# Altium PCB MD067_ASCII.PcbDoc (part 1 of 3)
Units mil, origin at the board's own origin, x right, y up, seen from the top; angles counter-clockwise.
Board outline 3650 x 4750 mil, 4 copper layers (Top Layer, GND Layer, Power Layer, Bottom Layer), stack 58.4 mil thick; 234 components, 118 nets, 586 pads, 972 vias.
Unrouted connection lines stored in the file: 42.
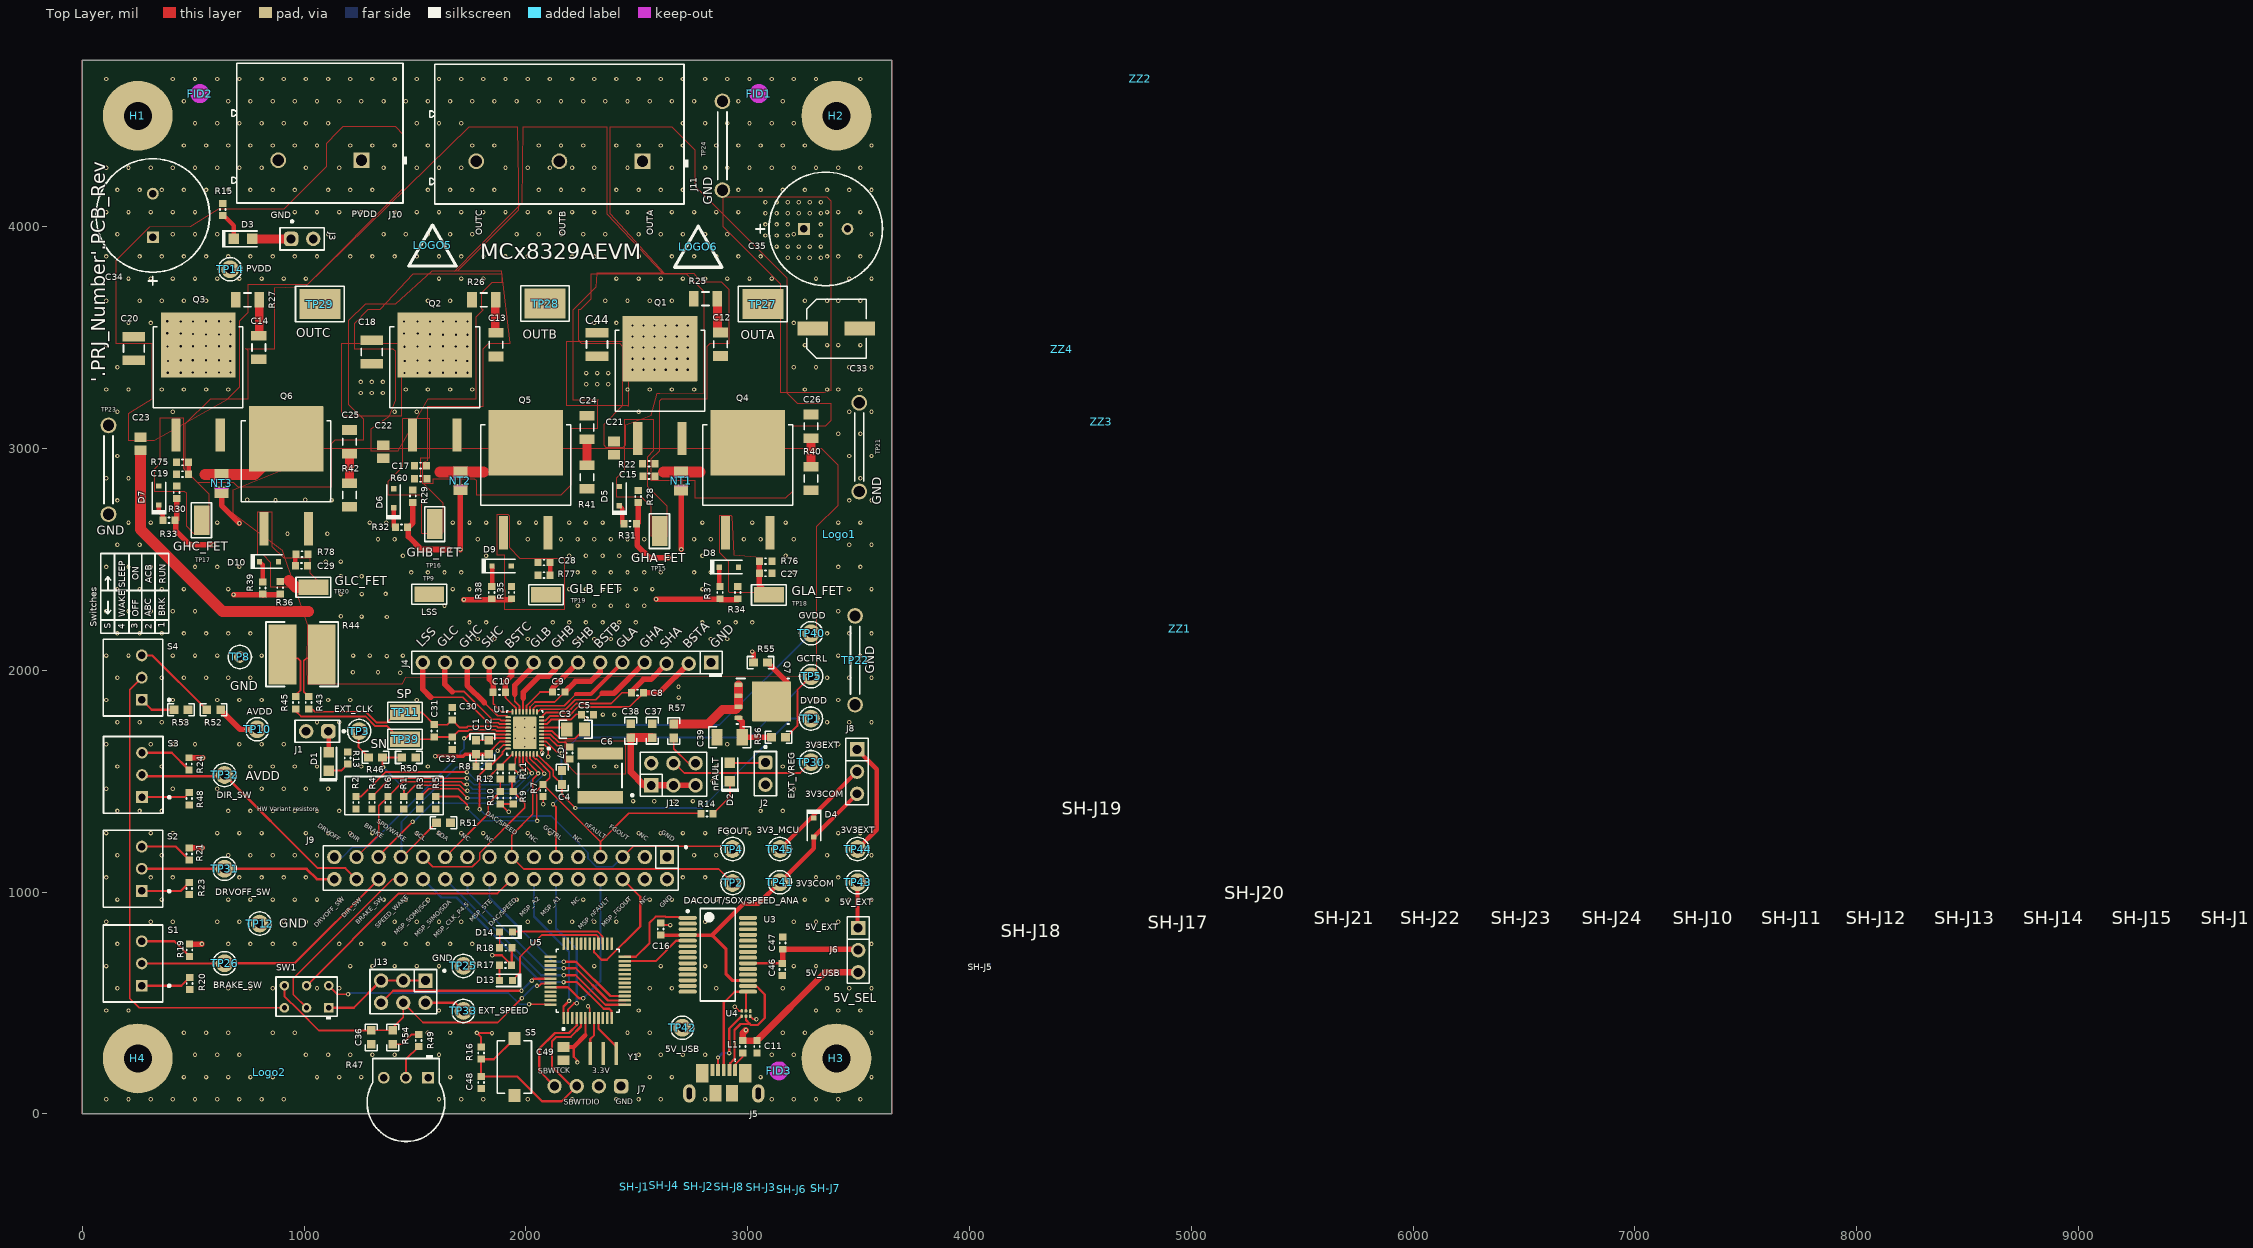
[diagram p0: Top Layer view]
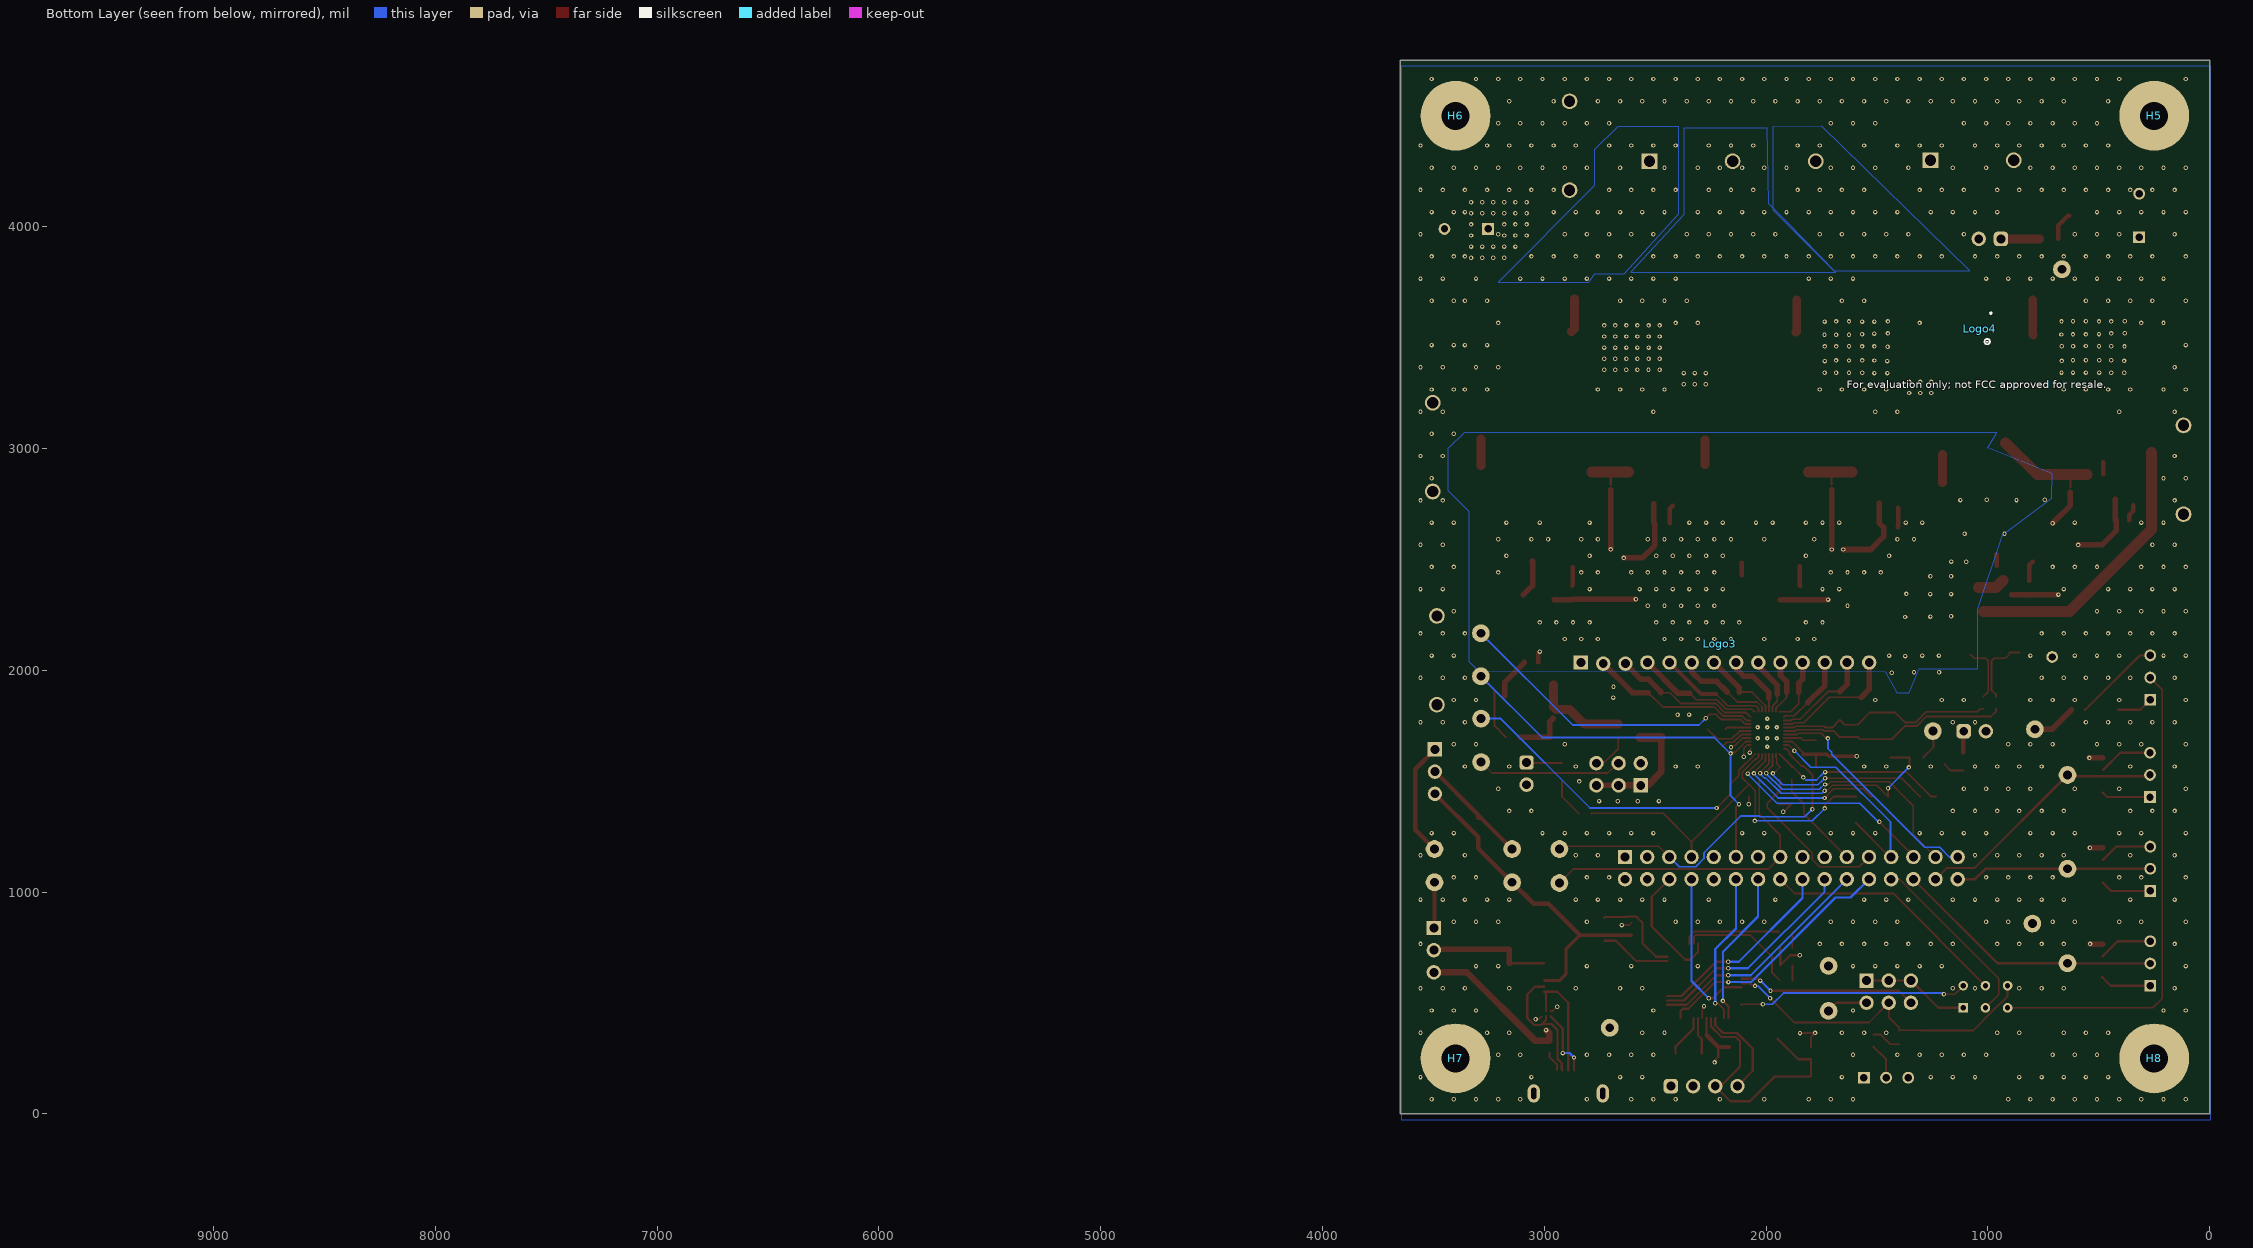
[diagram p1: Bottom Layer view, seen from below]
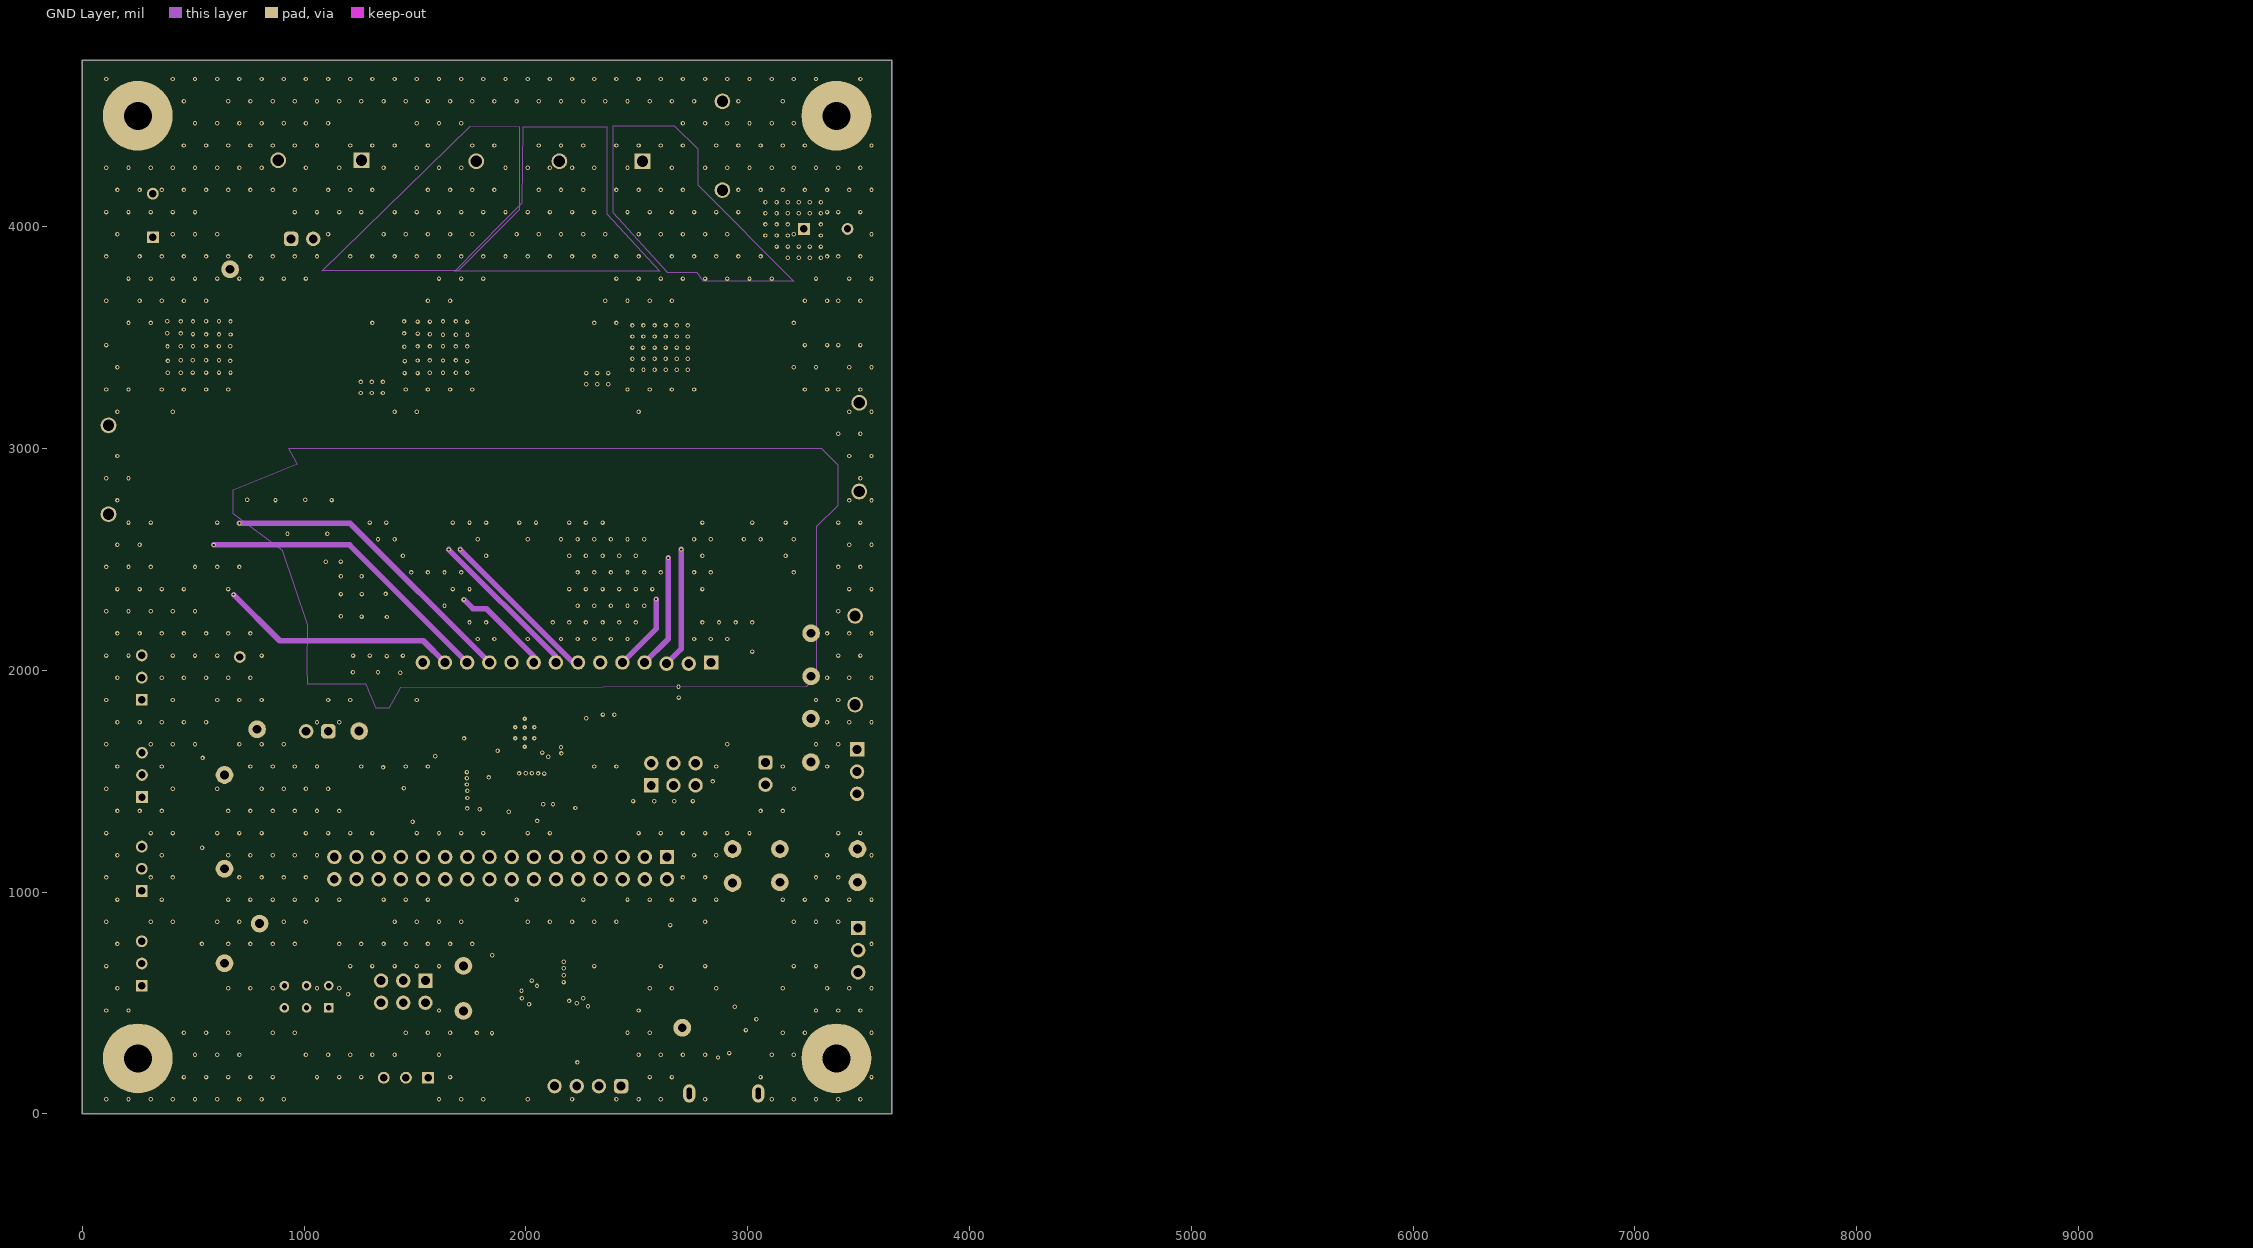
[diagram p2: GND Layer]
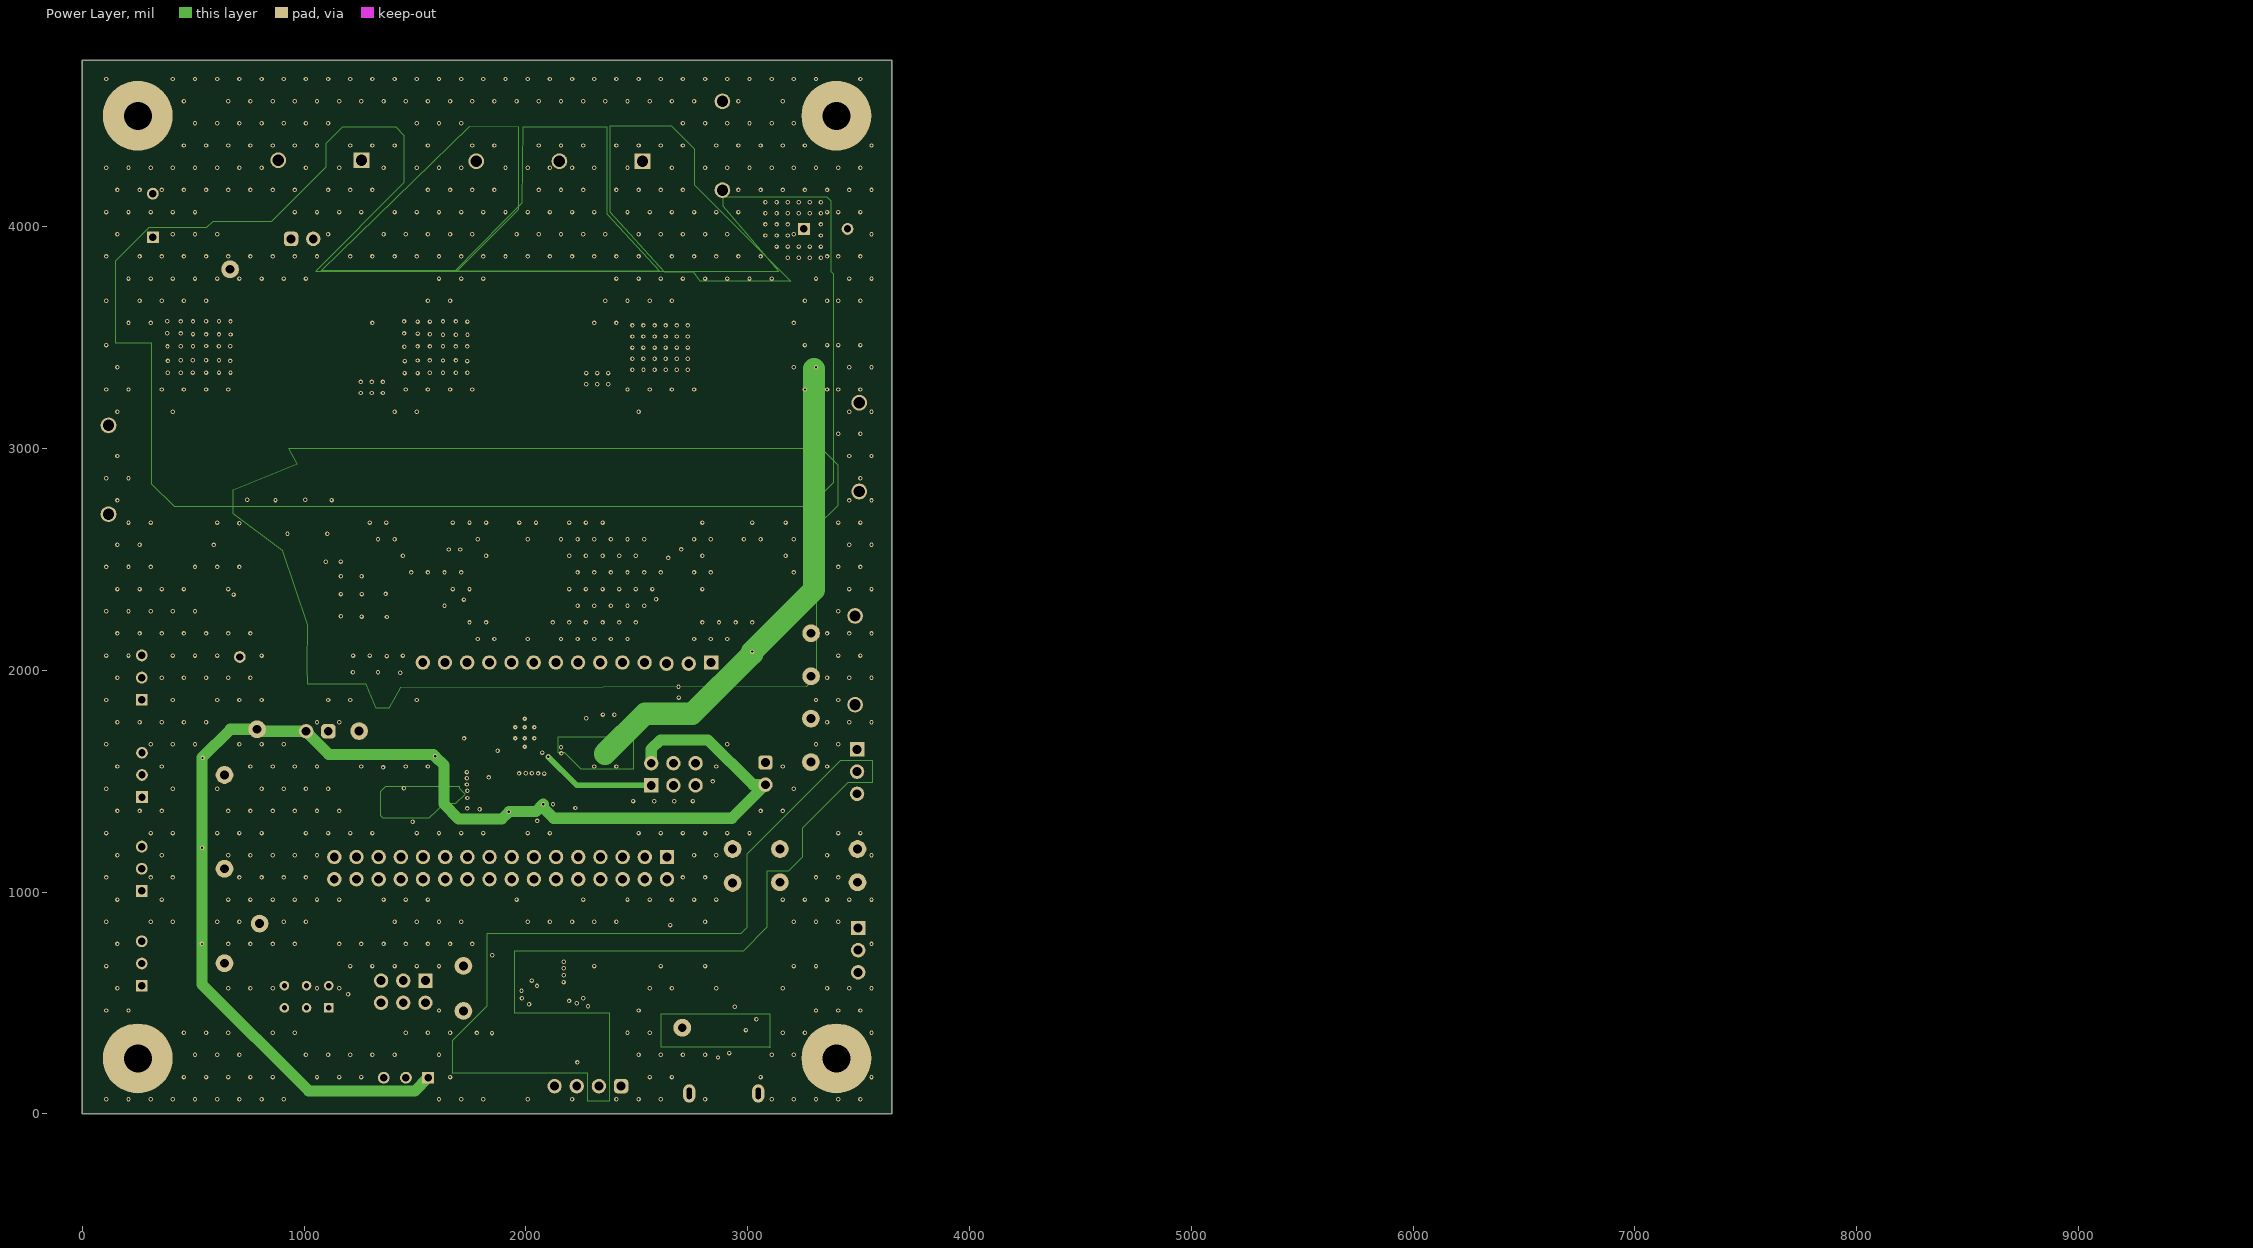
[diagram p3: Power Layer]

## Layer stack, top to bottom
Top Solder: solder mask 0.4, Solder Resist, Dk 3.5
Top Layer: signal copper 2.8
Dielectric 2: core 10, FR-4, Dk 4.8
GND Layer: signal copper 1.4
Dielectric 1: prepreg 30, FR-4, Dk 4.2
Power Layer: signal copper 1.4
Dielectric 3: core 10, FR-4, Dk 4.8
Bottom Layer: signal copper 2.8
Solder Side: solder mask 0.4, Solder Resist, Dk 3.5

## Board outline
0,0 3650,0 3650,4750 0,4750

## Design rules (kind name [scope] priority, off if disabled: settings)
AcuteAngle [All] p0: scope1count=1 scope1_0_kind=Board scope1_0_value=Board scope2count=1 scope2_0_kind=Board scope2_0_value=Board commentlength=0 minimum=4.50000000000000E+0001
AcuteAngle [All] p1: minimum=4.50000000000000E+0001 checktracksonly=FALSE
AssemblyTestPointUsage [All] p0: scope1count=1 scope1_0_kind=Board scope1_0_value=Board scope2count=1 scope2_0_kind=Board scope2_0_value=Board commentlength=0
AssemblyTestPointUsage [All] p1: valid=2
AssemblyTestpoint [All] p0: scope1count=1 scope1_0_kind=Board scope1_0_value=Board scope2count=1 scope2_0_kind=Board scope2_0_value=Board commentlength=0
BoardOutlineClearance [All] p0 off: scope1count=1 scope1_0_kind=Board scope1_0_value=Board scope2count=1 scope2_0_kind=Board scope2_0_value=Board commentlength=172 gap=50 // Protel DXP Scope 1 Expression Was: OnCopper and Not InComponentClass('Logo') and not InComponentClass('FiducialMark') and not InRegion(1000,500,4000,800) and not InPoly
BoardOutlineClearance BoardOutlineClearance_Poly [All] p0 off: scope1count=1 scope1_0_kind=Board scope1_0_value=Board scope2count=1 scope2_0_kind=Board scope2_0_value=Board commentlength=58 gap=25 // Protel DXP Scope 1 Expression Was: OnCopper and IsPoly
BoardOutlineClearance BoardOutlineClearance_MountingHoles [All] p0 off: scope1count=1 scope1_0_kind=Board scope1_0_value=Board scope2count=1 scope2_0_kind=Board scope2_0_value=Board commentlength=86 gap=39.37 // Protel DXP Scope 1 Expression Was: OnCopper and InComponentClass('Mounting Holes')
BoardOutlineClearance BoardOutlineClearance_MountingHoles [OnCopper and InComponentClass('Mounting Holes')] p1: gap=39.37 ignorepadtopadclearanceinfootprint=FALSE
BoardOutlineClearance BoardOutlineClearance_Poly [OnCopper and IsPoly] p2: gap=25 ignorepadtopadclearanceinfootprint=FALSE
BoardOutlineClearance [OnCopper and Not InComponentClass('Logo') and not InComponentClass('FiducialMark') and not InRegion(1000,500,4000,800) and not InPoly] p3: gap=50 ignorepadtopadclearanceinfootprint=FALSE
Clearance [All] p0: scope1count=1 scope1_0_kind=Board scope1_0_value=Board scope2count=1 scope2_0_kind=Board scope2_0_value=Board commentlength=0 gap=7.87
Clearance Clearance_FiducialMark [All] p0 off: scope1count=1 scope1_0_kind=Board scope1_0_value=Board scope2count=1 scope2_0_kind=Board scope2_0_value=Board commentlength=81 gap=0 // Protel DXP Scope 2 Expression Was: IsPad and InComponentClass('FiducialMark')
Clearance Clearance_Poly [All] p0 off: scope1count=1 scope1_0_kind=Board scope1_0_value=Board scope2count=1 scope2_0_kind=Board scope2_0_value=Board commentlength=48 gap=10 // Protel DXP Scope 1 Expression Was: InPolygon
Clearance Clearance_Keepouts [All] p0 off: scope1count=1 scope1_0_kind=Board scope1_0_value=Board scope2count=1 scope2_0_kind=Board scope2_0_value=Board commentlength=99 gap=0 // Protel DXP Scope 2 Expression Was: ((IsTrack Or IsArc) And Not InPoly) And IsFree and IsKeepOut
Clearance Clearance_Keepouts [((IsTrack Or IsArc) And Not InPoly) And IsFree and IsKeepOut vs ((IsTrack Or IsArc) And Not InPoly) And IsFree and IsKeepOut] p1: gap=0 ignorepadtopadclearanceinfootprint=FALSE
Clearance Clearance_Poly [InPolygon] p2: gap=10 ignorepadtopadclearanceinfootprint=TRUE
Clearance Clearance_FiducialMark [IsKeepOut and InComponentClass('FiducialMark') vs IsPad and InComponentClass('FiducialMark')] p3: gap=0 ignorepadtopadclearanceinfootprint=FALSE
Clearance [All] p4: gap=7.87 ignorepadtopadclearanceinfootprint=TRUE
ComponentClearance [All] p0: scope1count=1 scope1_0_kind=Board scope1_0_value=Board scope2count=1 scope2_0_kind=Board scope2_0_value=Board commentlength=0 gap=30 collisioncheckmode=3
ComponentClearance ComponentClearance_THtoTH [All] p0 off: scope1count=1 scope1_0_kind=Board scope1_0_value=Board scope2count=1 scope2_0_kind=Board scope2_0_value=Board commentlength=54 gap=30 collisioncheckmode=3 // Protel DXP Scope 2 Expression Was: IsThruComponent
ComponentClearance ComponentClearance_THtoSMT [All] p0 off: scope1count=1 scope1_0_kind=Board scope1_0_value=Board scope2count=1 scope2_0_kind=Board scope2_0_value=Board commentlength=53 gap=40 collisioncheckmode=3 // Protel DXP Scope 2 Expression Was: IsSMTComponent
ComponentClearance ComponentClearance_SmallPassives [All] p0 off: scope1count=1 scope1_0_kind=Board scope1_0_value=Board scope2count=1 scope2_0_kind=Board scope2_0_value=Board commentlength=508 gap=14.96 collisioncheckmode=3 // Protel DXP Scope 2 Expression Was: HasFootprint('0201*') or HasFootprint('0402*') or HasFootprint('0508') or HasFootprint('0603*') or HasFootprint('0612') or HasFootprint('0805*') or HasFootprint('0815*') or HasFootprint('0830*') or HasFootprint('1206*') or HasFootprint('1210*') or HasFootprint('1808*') or HasFootprint('1812*') or HasFootprint('1825*') or HasFootprint('2010*') or HasFootprint('2220*') or HasFootprint('2225*') or HasFootprint('2512*') or HasFootprint('2728*') or HasFootprint('3518*')
ComponentClearance ComponentClearance_MountingHoles [All] p0: scope1count=1 scope1_0_kind=ComponentClass scope1_0_value="Mounting Holes" scope2count=1 scope2_0_kind=Board scope2_0_value=Board commentlength=0 gap=10 collisioncheckmode=3
ComponentClearance ComponentClearance_ScrewToNut [All] p0 off: scope1count=1 scope1_0_kind=Board scope1_0_value=Board scope2count=1 scope2_0_kind=Board scope2_0_value=Board commentlength=71 gap=5 collisioncheckmode=3 // Protel DXP Scope 2 Expression Was: (HasFootprint('Keystone_1902C'))
ComponentClearance ComponentClearance_Logo [All] p0: scope1count=1 scope1_0_kind=ComponentClass scope1_0_value=Logo scope2count=1 scope2_0_kind=Board scope2_0_value=Board commentlength=0 gap=20 collisioncheckmode=3
ComponentClearance ComponentClearance_Shunt [All] p0: scope1count=1 scope1_0_kind=ComponentClass scope1_0_value=Header scope2count=1 scope2_0_kind=ComponentClass scope2_0_value=Shunt commentlength=0 gap=0 collisioncheckmode=3
ComponentClearance ComponentClearance_MountingHoles_FiducialMarks [All] p0: scope1count=1 scope1_0_kind=ComponentClass scope1_0_value="Mounting Holes" scope2count=1 scope2_0_kind=ComponentClass scope2_0_value=FiducialMark commentlength=0 gap=50 collisioncheckmode=3
ComponentClearance ComponentClearance_MountingHoles_FiducialMarks [InComponentClass('Mounting Holes') vs InComponentClass('FiducialMark')] p1: gap=50 collisioncheckmode=3 verticalgap=10 showdistances=FALSE
ComponentClearance ComponentClearance_Shunt [InComponentClass('Header') vs InComponentClass('Shunt')] p2: gap=0 collisioncheckmode=3 verticalgap=0 showdistances=FALSE
ComponentClearance ComponentClearance_Logo [InComponentClass('Logo')] p3: gap=20 collisioncheckmode=3 verticalgap=10 showdistances=FALSE
ComponentClearance ComponentClearance_ScrewToNut [(HasFootprint('NY PMS 440 0025 PH')) vs (HasFootprint('Keystone_1902C'))] p4: gap=5 collisioncheckmode=3 verticalgap=10 showdistances=FALSE
ComponentClearance ComponentClearance_MountingHoles [InComponentClass('Mounting Holes')] p5: gap=10 collisioncheckmode=3 verticalgap=100000 showdistances=FALSE
ComponentClearance ComponentClearance_SmallPassives [HasFootprint('0201*') or HasFootprint('0402*') or HasFootprint('0508') or HasFootprint('0603*') or HasFootprint('0612') or HasFootprint('0805*') or HasFootprint('0815*') or HasFootprint('0830*') or HasFootprint('1206*') or HasFootprint('1210*') or HasFootprint('1808*') or HasFootprint('1812*') or HasFootprint('1825*') or HasFootprint('2010*') or HasFootprint('2220*') or HasFootprint('2225*') or HasFootprint('2512*') or HasFootprint('2728*') or HasFootprint('3518*') vs HasFootprint('0201*') or HasFootprint('0402*') or HasFootprint('0508') or HasFootprint('0603*') or HasFootprint('0612') or HasFootprint('0805*') or HasFootprint('0815*') or HasFootprint('0830*') or HasFootprint('1206*') or HasFootprint('1210*') or HasFootprint('1808*') or HasFootprint('1812*') or HasFootprint('1825*') or HasFootprint('2010*') or HasFootprint('2220*') or HasFootprint('2225*') or HasFootprint('2512*') or HasFootprint('2728*') or HasFootprint('3518*')] p6: gap=14.96 collisioncheckmode=3 verticalgap=10 showdistances=FALSE
ComponentClearance ComponentClearance_THtoSMT [IsThruComponent vs IsSMTComponent] p7: gap=40 collisioncheckmode=3 verticalgap=30 showdistances=FALSE
ComponentClearance ComponentClearance_THtoTH [IsThruComponent vs IsThruComponent] p8: gap=30 collisioncheckmode=3 verticalgap=30 showdistances=FALSE
ComponentClearance [All] p9: gap=30 collisioncheckmode=3 verticalgap=10 showdistances=FALSE
DiffPairsRouting [All] p0: scope1count=1 scope1_0_kind=Board scope1_0_value=Board scope2count=1 scope2_0_kind=Board scope2_0_value=Board commentlength=0
DiffPairsRouting [All] p1: maxlimit=100 minlimit=10 mostfreqgap=10 toplayer_minwidth=15 toplayer_maxwidth=15 toplayer_prefwidth=15 midlayer1_minwidth=15 midlayer1_maxwidth=15 midlayer1_prefwidth=15 midlayer2_minwidth=15 midlayer2_maxwidth=15 midlayer2_prefwidth=15 bottomlayer_minwidth=15 bottomlayer_maxwidth=15 bottomlayer_prefwidth=15 maxuncoupledlength=1000
FabricationTestPointUsage TestPointUsage [All] p0: scope1count=1 scope1_0_kind=Board scope1_0_value=Board scope2count=1 scope2_0_kind=Board scope2_0_value=Board commentlength=0 valid=2 allowmultiple=FALSE
FabricationTestPointUsage TestPointUsage [All] p1: valid=2 allowmultiple=FALSE
FabricationTestpoint Testpoint [All] p0: scope1count=1 scope1_0_kind=Board scope1_0_value=Board scope2count=1 scope2_0_kind=Board scope2_0_value=Board commentlength=0 side=3 testpointundercomponent=TRUE minsize=40 maxsize=100 preferedsize=60 minholesize=0 maxholesize=40 preferedholesize=32 testpointgrid=1
FabricationTestpoint Testpoint [All] p1: side=3 testpointundercomponent=TRUE minsize=40 maxsize=100 preferedsize=60 minholesize=0 maxholesize=40 preferedholesize=32 testpointgrid=1 allowsidetop=TRUE allowsidebottom=TRUE usegrid=TRUE gridtolerance=0.01
FanoutControl Fanout_Small [All] p0 off: scope1count=1 scope1_0_kind=Board scope1_0_value=Board scope2count=1 scope2_0_kind=Board scope2_0_value=Board commentlength=84 // Protel DXP Scope 1 Expression Was: (CompPinCount < 5)   Fanout_Small (Default Rule)
FanoutControl Fanout_Default [All] p0: scope1count=1 scope1_0_kind=Board scope1_0_value=Board scope2count=1 scope2_0_kind=Board scope2_0_value=Board commentlength=30 // Fanout_Default (Default Rule)
FanoutControl Fanout_SOIC [All] p0 off: scope1count=1 scope1_0_kind=Board scope1_0_value=Board scope2count=1 scope2_0_kind=Board scope2_0_value=Board commentlength=71 // Protel DXP Scope 1 Expression Was: IsSOIC   Fanout_SOIC (Default Rule)
FanoutControl Fanout_BGA [All] p0 off: scope1count=1 scope1_0_kind=Board scope1_0_value=Board scope2count=1 scope2_0_kind=Board scope2_0_value=Board commentlength=69 // Protel DXP Scope 1 Expression Was: IsBGA   Fanout_BGA (Default Rule)
FanoutControl Fanout_LCC [All] p0 off: scope1count=1 scope1_0_kind=Board scope1_0_value=Board scope2count=1 scope2_0_kind=Board scope2_0_value=Board commentlength=69 // Protel DXP Scope 1 Expression Was: IsLCC   Fanout_LCC (Default Rule)
FanoutControl Fanout_LCC [IsLCC] p1: bgadir=Out bgaviamode=Centered fanoutstyle=Auto fanoutdirection=Alternating viagrid=1 // Fanout_LCC (Default Rule)
FanoutControl Fanout_BGA [IsBGA] p2: bgadir=Out bgaviamode=Centered fanoutstyle=Auto fanoutdirection=Alternating viagrid=1 // Fanout_BGA (Default Rule)
FanoutControl Fanout_Default [All] p4: bgadir=Out bgaviamode=Centered fanoutstyle=Auto fanoutdirection=Alternating viagrid=1 // Fanout_Default (Default Rule)
FanoutControl Fanout_Small [(CompPinCount < 5)] p5: bgadir=Out bgaviamode=Centered fanoutstyle=Auto fanoutdirection=OutThenIn viagrid=1 // Fanout_Small (Default Rule)
Height [All] p0 off: scope1count=1 scope1_0_kind=Board scope1_0_value=Board scope2count=1 scope2_0_kind=Board scope2_0_value=Board commentlength=0
Height [All] p1 off: minheight=0 maxheight=1000 prefheight=500
HoleSize [All] p0: scope1count=1 scope1_0_kind=Board scope1_0_value=Board scope2count=1 scope2_0_kind=Board scope2_0_value=Board commentlength=0 absolutevalues=TRUE maxlimit=250 minlimit=7.87 maxpercent=80.000 minpercent=20.000
HoleSize [All] p1: absolutevalues=TRUE maxlimit=250 minlimit=7.87 maxpercent=80.000 minpercent=20.000
HoleToHoleClearance [All] p0: scope1count=1 scope1_0_kind=Board scope1_0_value=Board scope2count=1 scope2_0_kind=Board scope2_0_value=Board commentlength=0
LayerPairs [All] p0: scope1count=1 scope1_0_kind=Board scope1_0_value=Board scope2count=1 scope2_0_kind=Board scope2_0_value=Board commentlength=0 enforce=TRUE
MinimumAnnularRing [All] p0: scope1count=1 scope1_0_kind=Board scope1_0_value=Board scope2count=1 scope2_0_kind=Board scope2_0_value=Board commentlength=0 minimumring=5
MinimumAnnularRing MinimumAnnularRing_ThermalPadVias [All] p0 off: scope1count=1 scope1_0_kind=Board scope1_0_value=Board scope2count=1 scope2_0_kind=Board scope2_0_value=Board commentlength=63 minimumring=5 // Protel DXP Scope 1 Expression Was: IsVia and InAnyComponent
MinimumAnnularRing MinimumAnnularRing_ThermalPadVias [IsVia and InAnyComponent] p1: minimumring=5
MinimumAnnularRing [All] p2: minimumring=5
MinimumSolderMaskSliver [All] p0: scope1count=1 scope1_0_kind=Board scope1_0_value=Board scope2count=1 scope2_0_kind=Board scope2_0_value=Board commentlength=0
MinimumSolderMaskSliver MinimumSolderMaskSliver_Logo [All] p0: scope1count=1 scope1_0_kind=ComponentClass scope1_0_value=Logo scope2count=1 scope2_0_kind=ComponentClass scope2_0_value=Logo commentlength=0
MinimumSolderMaskSliver MinimumSolderMaskSliver_Logo [InComponentClass('Logo') vs InComponentClass('Logo')] p1: minsoldermaskwidth=0.7
MinimumSolderMaskSliver [All] p2: minsoldermaskwidth=3.94
NetAntennae [All] p0: scope1count=1 scope1_0_kind=Board scope1_0_value=Board scope2count=1 scope2_0_kind=Board scope2_0_value=Board commentlength=0
PasteMaskExpansion [All] p0: scope1count=1 scope1_0_kind=Board scope1_0_value=Board scope2count=1 scope2_0_kind=Board scope2_0_value=Board commentlength=0 expansion=0
PlaneClearance [All] p0: scope1count=1 scope1_0_kind=Board scope1_0_value=Board scope2count=1 scope2_0_kind=Board scope2_0_value=Board commentlength=0 clearance=20
PlaneConnect [All] p0: scope1count=1 scope1_0_kind=Board scope1_0_value=Board scope2count=1 scope2_0_kind=Board scope2_0_value=Board commentlength=0 planeconnectstyle=Relief reliefexpansion=10 reliefentries=4 reliefconductorwidth=10 reliefairgap=10
PlaneConnect [All] p1: planeconnectstyle=Relief reliefexpansion=10 reliefentries=4 reliefconductorwidth=10 reliefairgap=10
PolygonConnect PolygonConnect_1 [All] p0: scope1count=1 scope1_0_kind=Board scope1_0_value=Board scope2count=1 scope2_0_kind=Board scope2_0_value=Board commentlength=0 connectstyle=Direct reliefconductorwidth=10 reliefentries=4 polygonreliefangle="90 Angle"
PolygonConnect PolygonConnect_1 [All] p1: connectstyle=Direct reliefconductorwidth=10 reliefentries=4 polygonreliefangle="90 Angle" airgapwidth=10
RoutingCorners [All] p0: scope1count=1 scope1_0_kind=Board scope1_0_value=Board scope2count=1 scope2_0_kind=Board scope2_0_value=Board commentlength=0 cornerstyle=45-Degree minsetback=100 maxsetback=100
RoutingLayers [All] p0: scope1count=1 scope1_0_kind=Board scope1_0_value=Board scope2count=1 scope2_0_kind=Board scope2_0_value=Board commentlength=0 top layer=Automatic mid layer 1=Automatic mid layer 2=Automatic bottom layer=Automatic
RoutingPriority [All] p0: scope1count=1 scope1_0_kind=Board scope1_0_value=Board scope2count=1 scope2_0_kind=Board scope2_0_value=Board commentlength=0
RoutingTopology [All] p0: scope1count=1 scope1_0_kind=Board scope1_0_value=Board scope2count=1 scope2_0_kind=Board scope2_0_value=Board commentlength=0 topology=Shortest
RoutingVias [All] p0: scope1count=1 scope1_0_kind=Board scope1_0_value=Board scope2count=1 scope2_0_kind=Board scope2_0_value=Board commentlength=0 holewidth=10 width=20 viastyle="Through Hole" minholewidth=10 minwidth=20 maxholewidth=10 maxwidth=20
RoutingVias ThermalPadVias [All] p0 off: scope1count=1 scope1_0_kind=Board scope1_0_value=Board scope2count=1 scope2_0_kind=Board scope2_0_value=Board commentlength=63 holewidth=7.87 width=19.68 viastyle="Through Hole" minholewidth=7.87 minwidth=19.68 maxholewidth=12.99 maxwidth=23.62 // Protel DXP Scope 1 Expression Was: IsVia and InAnyComponent
RoutingVias ThermalPadVias [IsVia and InAnyComponent] p1: holewidth=7.87 width=19.68 viastyle="Through Hole" minholewidth=7.87 minwidth=19.68 maxholewidth=12.99 maxwidth=23.62
RoutingVias [All] p2: holewidth=10 width=20 viastyle="Through Hole" minholewidth=10 minwidth=20 maxholewidth=10 maxwidth=20
ShortCircuit [All] p0: scope1count=1 scope1_0_kind=Board scope1_0_value=Board scope2count=1 scope2_0_kind=Board scope2_0_value=Board commentlength=0 allowed=FALSE
SilkToBoardRegionClearance [All] p0 off: scope1count=1 scope1_0_kind=Board scope1_0_value=Board scope2count=1 scope2_0_kind=Board scope2_0_value=Board commentlength=130 // Protel DXP Scope 1 Expression Was: Not ((IsComment or IsDesignator) And (Hide <> 'False')) and not InRegion(1000,500,4000,800)
SilkToBoardRegionClearance [Not ((IsComment or IsDesignator) And (Hide <> 'False')) and not InRegion(1000,500,4000,800)] p1:
SilkToSilkClearance [All] p0: scope1count=1 scope1_0_kind=Board scope1_0_value=Board scope2count=1 scope2_0_kind=Board scope2_0_value=Board commentlength=0
SilkToSilkClearance SilkToSilkClearance_Pb-FreeLogo [All] p0 off: scope1count=1 scope1_0_kind=Board scope1_0_value=Board scope2count=1 scope2_0_kind=Board scope2_0_value=Board commentlength=120 // Protel DXP Scope 2 Expression Was: (HasFootprint('Pb-Free_Overlay_Medium') OR HasFootprint('Pb-Free_Overlay_Small'))
SilkToSilkClearance SilkToSilkClearance_Pb-FreeLogo [(HasFootprint('Pb-Free_Overlay_Medium') OR HasFootprint('Pb-Free_Overlay_Small')) vs (HasFootprint('Pb-Free_Overlay_Medium') OR HasFootprint('Pb-Free_Overlay_Small'))] p1: silktosilkclearance=0
SilkToSilkClearance [All] p2: silktosilkclearance=1
SilkToSolderMaskClearance "Silk to Solder Mask Opening" [All] p0: scope1count=1 scope1_0_kind=Board scope1_0_value=Board scope2count=1 scope2_0_kind=Board scope2_0_value=Board commentlength=0
SilkToSolderMaskClearance SilkToComponentPadClearance [All] p0 off: scope1count=1 scope1_0_kind=Board scope1_0_value=Board scope2count=1 scope2_0_kind=Board scope2_0_value=Board commentlength=87 // Protel DXP Scope 1 Expression Was: (IsPad or IsFill or IsRegion) and InAnycomponent
SilkToSolderMaskClearance SilkToComponentPadClearance [(IsPad or IsFill or IsRegion) and InAnycomponent] p1: minsilkscreentomaskgap=2 clearancetoexposedcopper=TRUE
SilkToSolderMaskClearance "Silk to Solder Mask Opening" [All] p2: minsilkscreentomaskgap=3.94 clearancetoexposedcopper=FALSE
SolderMaskExpansion [All] p0: scope1count=1 scope1_0_kind=Board scope1_0_value=Board scope2count=1 scope2_0_kind=Board scope2_0_value=Board commentlength=0 expansion=1.97
SolderMaskExpansion [All] p1: expansion=1.97
UnRoutedNet [All] p0: scope1count=1 scope1_0_kind=Board scope1_0_value=Board scope2count=1 scope2_0_kind=Board scope2_0_value=Board commentlength=0
UnRoutedNet [All] p1: checkbadconnections=TRUE
UnpouredPolygon [All] p0: scope1count=1 scope1_0_kind=Board scope1_0_value=Board scope2count=1 scope2_0_kind=Board scope2_0_value=Board commentlength=0
Width [All] p0: scope1count=1 scope1_0_kind=Board scope1_0_value=Board scope2count=1 scope2_0_kind=Board scope2_0_value=Board commentlength=0 maxlimit=100 minlimit=6 preferedwidth=10
Width [All] p1: maxlimit=100 minlimit=6 preferedwidth=10 checkconnectedcopper=TRUE
13 further rules are at their usual default settings.

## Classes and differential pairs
component class MD067_INTERFACE: C11 C16 C46 C47 C48 C49 D4 D13 D14 J5 J6 J7 J8 J9 L1 R16 R17 R18 S5 SH-J4 SH-J5 SH-J6 SH-J10 SH-J11 SH-J12 SH-J13 SH-J14 SH-J15 SH-J16 SH-J17 SH-J18 SH-J19 SH-J20 SH-J21 SH-J22 SH-J23 SH-J24 TP41 TP42 TP43 TP44 TP45 U3 U4 U5 Y1
component class Shunt: SH-J1 SH-J2 SH-J3 SH-J4 SH-J5 SH-J6 SH-J7 SH-J8 SH-J10 SH-J11 SH-J12 SH-J13 SH-J14 SH-J15 SH-J16 SH-J17 SH-J18 SH-J19 SH-J20 SH-J21 SH-J22 SH-J23 SH-J24
component class MD067_POWER_AND_CONNECTORS: C33 C34 C35 C36 C39 GND1 GND2 GND3 J10 J11 J12 J13 Q7 R19 R20 R21 R23 R24 R47 R48 R49 R52 R53 R54 R55 R56 R57 S1 S2 S3 S4 SH-J7 SH-J8 SW1 TP8 TP12 TP21 TP22 TP23 TP24 TP25 TP26 TP27 TP28 TP29 TP30 TP31 TP32 TP33 TP38
component class MD067_FETS_AND_POWER_STAGE: C12 C13 C14 C15 C17 C18 C19 C20 C21 C22 C23 C24 C25 C26 C27 C28 C29 C30 C31 C32 C44 D5 D6 D7 D8 D9 D10 NT1 NT2 NT3 Q1 Q2 Q3 Q4 Q5 Q6 R22 R25 R26 R27 R28 R29 R30 R31 R32 R33 R34 R35 R36 R37 R38 R39 R40 R41 R42 R43 R44 R45 R60 R75 R76 R77 R78 TP15 TP16 TP17 TP18 TP19 TP20
component class MD067_DRIVER: C1 C2 C3 C4 C5 C6 C7 C8 C9 C10 C37 C38 D1 D2 D3 J1 J2 J3 J4 R1 R2 R3 R4 R5 R6 R7 R8 R9 R10 R11 R12 R13 R14 R15 R46 R50 R51 SH-J1 SH-J2 SH-J3 TP1 TP2 TP3 TP4 TP5 TP9 TP10 TP11 TP14 TP39 TP40 U1
component class Header: J1 J2 J3 J4 J6 J7 J8 J9 J12 J13
component class "Mounting Holes": H5 H6 H7 H8
component class Logo: Logo2
component class MD067_HARDWARE: FID1 FID2 FID3 H1 H2 H3 H4 H5 H6 H7 H8 Logo1 Logo2 Logo3 Logo4 LOGO5 LOGO6 ZZ1 ZZ2 ZZ3 ZZ4
component class FiducialMark: FID1 FID2 FID3
component class AssemblyNote: ZZ1 ZZ2 ZZ3 ZZ4

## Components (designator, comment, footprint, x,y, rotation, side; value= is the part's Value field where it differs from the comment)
C1 "C0603C106M9PACTU" 0603 1775,1653 r90 top
C2 "C0603C104K9PAC7867" 0603 1832.49,1653 r90 top
C3 "GRM21BR72A474KA73L" 0805_HV 2224,1734 r0 top
C4 "GRM188R60J105KA01D" 0603 2163,1516.46 r90 top
C5 "C1608X5R1E106M080AC" 0603L 2278,1800 r0 top
C6 "22201C106MAT2A" 2220_280L 2335,1526 r270 top
C7 "GRM188R72A104KA35J" 0603L 2197,1627.28 r270 top
C8 "C1608X5R1E105K080AC" 0603L 2503,1899 r0 top
C9 "C1608X5R1E105K080AC" 0603L 2147.56,1902.13 r180 top
C10 "C1608X5R1E105K080AC" 0603L 1880,1901 r180 top
C11 "0603ZC104KAT2A" 0603L 3042,303 r270 top
C12 "12061C392KAZ2A" 1206L 2877.09,3470 r90 top
C13 "12061C392KAZ2A" 1206L 1865,3467.91 r90 top
C14 "12061C392KAZ2A" 1206L 795,3455 r90 top
C15 "GRM188R71H202KA01D" 0603L 2555,2874.88 r0 top
C16 "0603ZC104KAT2A" 0603L 2607,833 r90 top
C17 "GRM188R71H202KA01D" 0603L 1524.12,2923 r0 top
C18 "GRM32DC72A475KE01L" 1210_220L 1305,3435 r270 top
C19 "GRM188R71H202KA01D" 0603L 452,2884 r0 top
C20 "GRM32DC72A475KE01L" 1210_220L 232.32,3450.75 r270 top
C21 "08051C103JAT2A" 0805L 2397.68,3001.97 r270 top
C22 "08051C103JAT2A" 0805L 1356.8,2985 r270 top
C23 "08051C103JAT2A" 0805L 261.85,3021.65 r270 top
C24 "12061C392KAZ2A" 1206L 2275,3095 r270 top
C25 "12061C392KAZ2A" 1206L 1205,3030 r270 top
C26 "12061C392KAZ2A" 1206L 3285,3100 r270 top
C27 "GRM188R71H202KA01D" 0603L 3081,2437 r0 top
C28 "GRM188R71H202KA01D" 0603L 2082,2486 r0 top
C29 "GRM188R71H202KA01D" 0603L 988,2471 r0 top
C30 "06031C331KAT2A" 0603L 1667,1804 r270 top
C31 "C1608NP01H103J080AA" 0603L 1587,1727 r270 top
C32 "06031C331KAT2A" 0603L 1667,1671 r270 top
C33 "EMZA800ADA100MF80G" CAPSMT_62_F80 3398.7,3540 r0 top
C34 "EKYB101ELL391MK35S" KYB_1250x3500 318,4050.57 r90 top
C35 "EKYB101ELL391MK35S" KYB_1250x3500 3351.57,3990 r0 top
C36 "0603ZC101KAT2A" 0603 1303.24,345 r270 top
C37 "C0603C106M9PACTU" 0603 2569,1727.61 r90 top
C38 "C0603C104K9PAC7867" 0603 2473,1727.61 r90 top
C39 "12065A202JAT2A" 1206 2918.82,1698 r180 top
C44 "GRM32DC72A475KE01L" 1210_220L 2320,3469 r270 top
C46 "GRM188Z71A475ME15D" 0603L 3156,651 r90 top
C47 "0603ZC104KAT2A" 0603L 3157,769.72 r90 top
C48 "885012206034" 0603L 1798,141 r270 top
C49 "885012207103" 0805L 2168.94,272 r270 top
D1 "AVDD" LTST-C170KGKT_Green 1110,1589 r270 top
D2 "nFAULT" LED_LTST-C170_Red 2920,1541 r270 top
D3 "PVDD" LTST-C170KGKT_Green 724.65,3945 r180 top
D4 "BAT165E6327HTSA1" SOD-323 3298,1291 r270 top
D5 "1N4448WX-TP" SOD-323 2421.3,2785.43 r90 top
D6 "1N4448WX-TP" SOD-323 1403.58,2775.59 r90 top
D7 "1N4448WX-TP" SOD-323 344.69,2788 r90 top
D8 "1N4448WX-TP" SOD-323 2915,2465 r0 top
D9 "1N4448WX-TP" SOD-323 1890.8,2470 r0 top
D10 "1N4448WX-TP" SOD-323 841.57,2489.83 r0 top
D13 "LTST-C190KRKT" LED_LTST-C190_Red 1910,602.05 r0 top
D14 "LTST-C190KRKT" LED_LTST-C190_Red 1911,820 r0 top
FID1 "Fiducial" Fiducial10-20 3050,4600 r0 top
FID2 "Fiducial" Fiducial10-20 530,4600 r0 top
FID3 "Fiducial" Fiducial10-20 3141,194 r0 top
H1 "1902E" "NY PMS 440 0025 PH" 250,4500 r0 top
H2 "1902E" "NY PMS 440 0025 PH" 3400,4500 r0 top
H3 "1902E" "NY PMS 440 0025 PH" 3400,250 r0 top
H4 "1902E" "NY PMS 440 0025 PH" 250,250 r0 top
H5 "NY PMS 440 0025 PH" Keystone_1902C 250,4500 r180 bottom
H6 "NY PMS 440 0025 PH" Keystone_1902C 3400,4500 r180 bottom
H7 "NY PMS 440 0025 PH" Keystone_1902C 3400,250 r180 bottom
H8 "NY PMS 440 0025 PH" Keystone_1902C 250,250 r180 bottom
J1 "TSW-102-07-G-S" TSW-102-07-G-S 1059,1725 r180 top
J2 "TSW-102-07-G-S" TSW-102-07-G-S 3080,1534 r270 top
J3 "TSW-102-07-G-S" TSW-102-07-G-S 991,3945 r0 top
J4 "TSW-114-07-G-S" TSW-114-07-G-S 2185,2035 r180 top
J5 "1051640001" Molex_1051640001 2892,35.19 r0 top
J6 "5V_SEL" PBC03SAAN 3498,738 r270 top
J7 "TSW-104-07-G-S" TSW-104-07-G-S 2279,125 r180 top
J8 "Header_3x1" PBC03SAAN 3493,1543 r270 top
J9 "TSW-116-07-G-D" TSW-116-07-G-D 1886,1108 r180 top
J10 "PVDD_IN" Phoenix_1902547 1071,4422 r180 top
J11 "MOTOR_OUT" Phoenix_1904150 2151,4417 r180 top
J12 "VREG_SEL" TSW-103-07-G-D 2665,1531 r0 top
J13 "Header_3x2" TSW-103-07-G-D 1447,550.79 r180 top
L1 "BLM18SG121TZ1D" 0603L 2977,303 r270 top
Logo1 "CE Mark" CE_Mark_5mm 3413,2613 r0 top
Logo2 "Texas Instruments" TI_Stacked_Overlay_Small 843,188 r0 top
Logo3 "FCC disclaimer" FCC_disclaimer 2208,2120 r180 bottom
Logo4 "WEEE logo" WEEE_Minimum 1037,3540 r180 bottom
LOGO5 "CAUTION HOT SURFACE" IEC_HotSurface_Small 1578.78,3915.26 r0 top
LOGO6 "CAUTION HOT SURFACE" IEC_HotSurface_Small 2776.96,3910.14 r0 top
NT1 "Net-Tie" Net-Tie_0805_HV_NoOverlay 2700,2853.5 r90 top net-tie
NT2 "Net-Tie" Net-Tie_0805_HV_NoOverlay 1704.76,2854.33 r90 top net-tie
NT3 "Net-Tie" Net-Tie_0805_HV_NoOverlay 627.77,2842.52 r90 top net-tie
Q1 "CSD18536KTTT" KTT0002A-MFG 2604.37,3350 r0 top
Q2 "CSD18536KTTT" KTT0002A-MFG 1589,3366 r0 top
Q3 "CSD18536KTTT" KTT0002A-MFG 521.92,3366.31 r0 top
Q4 "CSD18536KTTT" KTT0002A-MFG 3000,2925 r0 top
Q5 "CSD18536KTTT" KTT0002A-MFG 1999.05,2925 r0 top
Q6 "CSD18536KTTT" KTT0002A-MFG 919,2943 r0 top
Q7 "CSD18534Q5A" DQJ0008A 3068.04,1860 r0 top
R1 "ERJ-3GEY0R00V" 0603L 1450,1402.8 r270 top
R2 "ERJ-3GEY0R00V" 0603L 1234,1402.8 r270 top
R3 "ERJ-3GEY0R00V" 0603L 1522,1402.8 r270 top
R4 "ERJ-3GEY0R00V" 0603L 1306,1402.8 r270 top
R5 "ERJ-3GEY0R00V" 0603L 1594,1402.8 r270 top
R6 "ERJ-3GEY0R00V" 0603L 1378,1402.8 r270 top
R7 "CRCW06035K10JNEA" 0603L 2077,1458.27 r90 top
R8 "CRCW06035K10JNEA" 0603L 1803,1568 r180 top
R9 "CRCW06035K10JNEA" 0603L 1943,1425 r270 top
R10 "CRCW06035K10JNEA" 0603L 1885,1425 r270 top
R11 "ERJ-3GEY0R00V" 0603L 1937.29,1536.29 r90 top
R12 "ERJ-3GEY0R00V" 0603L 1884.29,1536.29 r90 top
R13 "RC0603JR-07820RL" 0603L 1196,1604.72 r270 top
R14 "RC0603JR-07820RL" 0603L 2816,1353 r0 top
R15 "RG1608P-202-B-T5" 0603L 633,4077 r270 top
R16 "RC0603JR-0747KL" 0603L 1798,274 r90 top
R17 "RC0603JR-07470RL" 0603L 1908,670 r0 top
R18 "RC0603JR-07470RL" 0603L 1909,748 r0 top
R19 "ERA-3ARW103V" 0603L 483,738 r90 top
R20 "ERA-3ARW103V" 0603L 484,588 r90 top
R21 "ERA-3ARW103V" 0603L 482,1172 r90 top
R22 "CRCW060310K0JNEA" 0603L 2554,2931 r180 top
R23 "ERA-3ARW103V" 0603L 482,1016 r90 top
R24 "ERA-3ARW103V" 0603L 481,1578 r90 top
R25 "CRCW12061R50FKEA" 1206L 2810,3675 r0 top
R26 "CRCW12061R50FKEA" 1206L 1810,3670 r0 top
R27 "CRCW12061R50FKEA" 1206L 745,3670 r0 top
R28 "CRCW060310R0JNEA" 0603L 2505.94,2783.19 r90 top
R29 "CRCW060310R0JNEA" 0603L 1490,2785 r90 top
R30 "CRCW060310R0JNEA" 0603L 425,2802.52 r90 top
R31 "CRCW060310R0JNEA" 0603L 2470,2660 r180 top
R32 "CRCW060310R0JNEA" 0603L 1438.45,2644.13 r180 top
R33 "CRCW060310R0JNEA" 0603L 390.42,2676.39 r180 top
R34 "CRCW060310R0JNEA" 0603L 2955,2350 r90 top
R35 "CRCW060310R0JNEA" 0603L 1935,2350 r90 top
R36 "CRCW060310R0JNEA" 0603L 891.77,2372.05 r90 top
R37 "CRCW060310R0JNEA" 0603L 2875,2350 r90 top
R38 "CRCW060310R0JNEA" 0603L 1845,2350 r90 top
R39 "CRCW060310R0JNEA" 0603L 813.03,2371.12 r90 top
R40 "CRCW12061R50FKEA" 1206L 3285,2865 r90 top
R41 "CRCW12061R50FKEA" 1206L 2275,2870.88 r90 top
R42 "CRCW12061R50FKEA" 1206L 1205,2790 r90 top
R43 "ERJ-3GEY0R00V" 0603L 1020,1854 r90 top
R44 "CSS2725FT1L00" CSS2725_001 991,2072 r0 top
R45 "ERJ-3GEY0R00V" 0603L 963,1854 r90 top
R46 "ERJ-3GEY0R00V" 0603 1322,1607 r0 top
R47 "3352T-1-253LF" Bourns_3352T 1459,163 r180 top
R48 "ERA-3ARW103V" 0603L 482,1421 r90 top
R49 "ERJ-3GEY0R00V" 0603L 1516,330.73 r270 top
R50 "RMCF0603FG1M00" 0603 1472,1607 r180 top
R51 "RT0603BRD07100KL" 0603 1628,1312 r180 top
R52 "ERA-3ARW103V" 0603 592,1822 r0 top
R53 "ERA-3ARW103V" 0603 445,1822 r180 top
R54 "RT0603BRD0747RL" 0603 1400,345 r270 top
R55 "ERJ-3GEY0R00V" 0603 3058,2035 r180 top
R56 "ERJ-3GEY0R00V" 0603 3139,1698 r180 top
R57 "ERJ-3GEY0R00V" 0603 2667,1725.87 r270 top
R60 "CRCW060310K0JNEA" 0603L 1525.59,2863 r180 top
R75 "CRCW060310K0JNEA" 0603L 452,2937 r180 top
R76 "CRCW060310K0JNEA" 0603L 3081,2492 r180 top
R77 "CRCW060310K0JNEA" 0603L 2082,2429 r180 top
R78 "CRCW060310K0JNEA" 0603L 989.82,2523.99 r180 top
S1 "SW_SPDT_COM2_1_3" SW_B12AP 228.63,677.95 r180 top
S2 "SW_SPDT_COM2_1_3" SW_B12AP 228.63,1105 r180 top
S3 "SW_SPDT_COM2_1_3" SW_B12AP 229.63,1528 r180 top
S4 "B12AP" SW_B12AP 228.63,1967 r180 top
S5 "SW_SPST-single" SW_434121025816 1948,211 r270 top
SH-J1 "SNT-100-BK-G" SNT-100-BK-G 2490,-329 r270 top
SH-J2 "SNT-100-BK-G" SNT-100-BK-G 2780,-326 r270 top
SH-J3 "SNT-100-BK-G" SNT-100-BK-G 3061,-332 r270 top
SH-J4 "SNT-100-BK-G" SNT-100-BK-G 2623,-323 r90 top
SH-J5 "SNT-100-BK-G" SNT-100-BK-G 4037,521 r90 top
SH-J6 "SNT-100-BK-G" SNT-100-BK-G 3198,-339 r90 top
SH-J7 "SNT-100-BK-G" SNT-100-BK-G 3351,-336 r90 top
SH-J8 "SNT-100-BK-G" SNT-100-BK-G 2917,-329 r270 top
SH-J10 "SNT-100-BK-G" SNT-100-BK-G 7211,725 r90 top
SH-J11 "SNT-100-BK-G" SNT-100-BK-G 7611,725 r90 top
SH-J12 "SNT-100-BK-G" SNT-100-BK-G 7991,725 r90 top
SH-J13 "SNT-100-BK-G" SNT-100-BK-G 8391,725 r90 top
SH-J14 "SNT-100-BK-G" SNT-100-BK-G 8791,725 r90 top
SH-J15 "SNT-100-BK-G" SNT-100-BK-G 9191,725 r90 top
SH-J16 "SNT-100-BK-G" SNT-100-BK-G 9591,725 r90 top
SH-J17 "SNT-100-BK-G" SNT-100-BK-G 4845,704 r90 top
SH-J18 "SNT-100-BK-G" SNT-100-BK-G 4181,667 r90 top
SH-J19 "SNT-100-BK-G" SNT-100-BK-G 4457,1218 r90 top
SH-J20 "SNT-100-BK-G" SNT-100-BK-G 5182,725 r90 top
SH-J21 "SNT-100-BK-G" SNT-100-BK-G 5592,725 r90 top
SH-J22 "SNT-100-BK-G" SNT-100-BK-G 5982,725 r90 top
SH-J23 "SNT-100-BK-G" SNT-100-BK-G 6391,725 r90 top
SH-J24 "SNT-100-BK-G" SNT-100-BK-G 6801,725 r90 top
SW1 "G22AP" SW_G2xAP 1011,528 r180 top
TP1 "DVDD" Keystone5000 3285,1782 r0 top
TP2 "DACOUT/SOX/SPEED_ANA" Keystone5002 2931.82,1041 r0 top
TP3 "EXT_CLK" Keystone5002 1248,1725.87 r180 top
TP4 "FGOUT" Keystone5002 2931.82,1194 r0 top
TP5 "GCTRL" Keystone5002 3286,1973 r90 top
TP8 "GND" Keystone5001#1 710.07,2060 r90 top
TP9 "LSS" Testpoint_Keystone_Miniature 1564,2342 r180 top
TP10 "AVDD" Keystone5000 788,1734 r0 top
TP11 "SP" Testpoint_Keystone_Miniature 1454.87,1810 r180 top
TP12 "GND" Keystone5001#2 799.38,858 r0 top
TP14 "PVDD" Keystone5000 666,3808 r90 top
TP15 "GHA_FET" Testpoint_Keystone_Miniature 2602.4,2627.01 r270 top
TP16 "GHB_FET" Testpoint_Keystone_Miniature 1588.09,2658.66 r90 top
TP17 "GHC_FET" Testpoint_Keystone_Miniature 537.44,2676.39 r270 top
TP18 "GLA_FET" Testpoint_Keystone_Miniature 3095,2339.62 r0 top
TP19 "GLB_FET" Testpoint_Keystone_Miniature 2090,2339.62 r180 top
TP20 "GLC_FET" Testpoint_Keystone_Miniature 1041.38,2374.02 r180 top
TP21 "GND" Harwin_D3082-05 3503,3006 r90 top
TP22 "GND" Harwin_D3082-05 3484,2045 r270 top
TP23 "GND" Harwin_D3082-05 118,2904 r270 top
TP24 "GND" Harwin_D3082-05 2886,4365 r270 top
TP25 "GND" Keystone5001#2 1718,667 r90 top
TP26 "BRAKE_SW" Keystone5002 641,679 r90 top
TP27 "OUTA" Testpoint_Keystone_Compact 3068,3651 r0 top
TP28 "OUTB" Testpoint_Keystone_Compact 2086,3653.31 r180 top
TP29 "OUTC" Testpoint_Keystone_Compact 1071,3651 r180 top
TP30 "EXT_VREG" Keystone5000 3285,1586 r0 top
TP31 "DRVOFF_SW" Keystone5002 641,1105 r0 top
TP32 "DIR_SW" Keystone5002 641,1528 r0 top
TP33 "EXT_SPEED" Keystone5002 1718,464 r90 top
TP39 "SN" Testpoint_Keystone_Miniature 1454.87,1689 r0 top
TP40 "GVDD" Keystone5000 3286,2167 r90 top
TP41 "3V3COM" Keystone5000 3145,1044 r90 top
TP42 "5V_USB" Keystone5000 2705,388 r90 top
TP43 "5V_EXT" Keystone5000 3495,1044 r90 top
TP44 "3V3EXT" Keystone5000 3495,1194 r90 top
TP45 "3V3_MCU" Keystone5000 3145,1194 r90 top
U1 "MCT8329A1I" REE0036A-MFG 1995,1718 r180 top
U3 "FT232RL" SSOP28_N 2865.17,717.2 r0 top
U4 "TPD4E004DRYR" DRY0006A 2992,452 r270 top
U5 "MSP430FR2355TPTR" PT0048A-MFG 2278,600 r90 top
Y1 "CSTCR4M00G55B-R0" Murata_CSTCR_G 2349,272 r0 top
ZZ1 "This Assembly Note is for PCB labels only" AssemblyNoteLabel 4947.75,2186.47 r90 top
ZZ2 "These assemblies are ESD sensitive, ESD precautions shall be observed." AssemblyNote 4770.59,4666.77 r90 top
ZZ3 "These assemblies must be clean and free from flux and all contaminants. Use of no clean flux is not acceptable." AssemblyNote 4593.42,3121.5 r90 top
ZZ4 "These assemblies must comply with workmanship standards IPC-A-610 Class 2, unless otherwise specified." AssemblyNote 4416.26,3446.31 r90 top

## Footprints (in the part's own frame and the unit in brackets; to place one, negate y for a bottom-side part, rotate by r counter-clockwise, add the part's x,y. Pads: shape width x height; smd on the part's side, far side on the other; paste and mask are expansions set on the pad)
0603 [mm] "0603 from SM-752 data"
  rect 1x0.95 smd: 1(-0.8,0) 2(0.8,0)
  silkscreen extent -1.52,-0.69 1.52,0.69
0603L [mm] "0603 from SM-752 data"
  rect 0.8x0.85 smd: 1(-0.7,0) 2(0.7,0)
  silkscreen extent -0.07,-0.33 0.07,0.33
0805_HV [mil] "0805 with 30mil clearance between pads"
  rect 50x63 smd: 1(-40,0) 2(40,0)
  silkscreen extent -74,-40 74,40
0805L [mm] "0805 from SM-752 data"
  rect 1.1x1.4 smd: 1(-0.75,0) 2(0.75,0)
1206 [mm] "1206 from SM-752 data"
  rect 1.3x1.85 smd: 1(-1.45,0) 2(1.45,0)
  silkscreen extent -2.4,-1.21 2.4,1.21
1206L [mm] "1206 from SM-752 data"
  rect 1.1x1.75 smd: 1(-1.35,0) 2(1.35,0)
  silkscreen extent -0.4,-0.77 0.4,0.77
1210_220L [mm] "1210"
  rect 1.1x2.6 smd: 1(-1.35,0) 2(1.35,0)
  silkscreen extent -0.4,-1.2 0.4,1.2
2220_280L [mm] "Chip Capacitor, Body 5.7x5.0mm, IPC High Density"
  rect 1.4x5.2 smd: 1(-2.5,0) 2(2.5,0)
  silkscreen extent -1.4,-2.5 1.4,2.5
AssemblyNote [mil] "Assembly Note"
AssemblyNoteLabel [mil] "Assembly Note for PCB Labels"
Bourns_3352T [mm] "TH, 3-Leads, Body 9.53x8.89mm, Pitch 2.54mm"
  rect 1.35x1.35 hole 0.85: 1(-2.54,0)
  round 1.35 hole 0.85: 2(0,0) 3(2.54,0)
  silkscreen extent -4.44,-2.6 4.44,7.31
CAPSMT_62_F80 [mm] "6.3 x 7.7mm:  Chemi-Con F80"
  rect 3.5x1.6 smd: 1(-2.7,0) 2(2.7,0)
  silkscreen extent -3.36,-3.4 3.44,3.4
CE_Mark_5mm [mil] "Minimum text height for CE Mark"
CSS2725_001 [mm] "STACKPOLE ELECTRONICS"
  rect 3.18x6.86 smd: 1(-2.25,0) 2(2.25,0)
  silkscreen extent -4.13,-3.7 4.13,3.7
DQJ0008A [mm] "SMD, 8-Leads, Body 5.75x4.9mm"
  rrect39% 0.91x0.51 smd paste-0.05 mask+0: 1(-2.795,1.905) 2(-2.795,0.635) 3(-2.795,-0.635) 4(-2.795,-1.905) 5(2.795,-1.905) 6(2.795,-0.635) 7(2.795,0.635) 8(2.795,1.905)
  rrect8% 1.58x1.25 on Top Paste: 9(-0.38,-1.45) 9(-0.38,0) 9(-0.38,1.45) 9(1.4,-1.45) 9(1.4,0) 9(1.4,1.45)
  rrect3% 3.48x4.47 on Top Solder: 9(0.55,0)
  rrect2% 4.49x4.57 smd paste-2.5 mask+0: 9(1.005,0)
  silkscreen extent -3,-2.6 3,2.6
DRY0006A [mm] "USON-6"
  rrect67% 0.45x0.3 smd paste-0.05 mask+0: 1(-0.275,0.5)
  rrect67% 0.4x0.3 smd paste-0.05 mask+0: 2(-0.3,0) 3(-0.3,-0.5) 4(0.3,-0.5) 5(0.3,0) 6(0.3,0.5)
FCC_disclaimer [mil]
Fiducial10-20 [mm]
  round 1 smd mask+0: 1(0,0)
  Top Layer keep-out circle w1.178: c0,0 r0.5
Harwin_D3082-05 [mm] "Shorting Plug, 10.16mm spacing, TH"
  round 1.8 hole 1.3: 1(-5.08,0) 2(5.08,0)
  silkscreen extent -3.9,-0.53 3.9,0.53
IEC_HotSurface_Small [mil]
  silkscreen extent -107,-93 107,92
Keystone5000 [mil] "For Keystone 500x miniature loop terminals"
  round 80 hole 40: 1(0,0)
  silkscreen extent -52,-52 52,52
Keystone5001#1 [mm] "For Keystone 500x miniature loop terminals"
  round 1.35 hole 0.85 paste+0: 1(0,0)
  silkscreen extent -1.33,-1.33 1.33,1.33
Keystone5001#2 [mm] "For Keystone 500x miniature loop terminals"
  round 2.032 hole 1.016: 1(0,0)
  silkscreen extent -1.33,-1.33 1.33,1.33
Keystone5002 [mil] "For Keystone 500x miniature loop terminals"
  round 80 hole 40: 1(0,0)
  silkscreen extent -52,-52 52,52
Keystone_1902C [mil] "Hex Standoff, 4-40 threaded, nylon"
  round 1 on Mech4: 0(0,0)
KTT0002A-MFG [mm]
  rrect10% 1.05x3.82 smd paste+0 mask+0: 1(-2.54,-7.755) 3(2.54,-7.755)
  rrect1% 8.55x7.48 smd paste-1000 mask+0: 4(0,2.545)
  silkscreen extent -5.13,-4.62 5.13,4.62
KYB_1250x3500 [mm] "TH, 2-Leads, Dia 12.5mm, Lead Spacing 5mm"
  rect 1.35x1.35 hole 0.85: 1(-2.5,0)
  round 1.35 hole 0.85: 2(2.5,0)
  silkscreen extent -8,-6.5 6.5,6.5
LED_LTST-C170_Red [mm] "LITE-ON"
  rect 1.2x1.2 smd: 1(-1.05,0) 2(1.05,0)
  silkscreen extent -1.6,-0.99 2.3,1.01
LED_LTST-C190_Red [mm] "Lite-On"
  rect 0.8x0.8 smd: 1(-0.75,0) 2(0.75,0)
  silkscreen extent -1.1,-0.8 1.8,0.8
LTST-C170KGKT_Green [mm] "LITE-ON"
  rect 1.2x1.2 smd: 1(-1.05,0) 2(1.05,0)
  silkscreen extent -1.6,-1.01 2.31,0.99
Molex_1051640001 [mm] "Receptacle, USB 2.0, Micro B, 5 Pos, 0.65mm Pitch, R/A, SMT"
  rrect22% 0.45x1.38 smd: 1(1.3,4.11) 2(0.65,4.11) 3(0,4.11) 4(-0.65,4.11) 5(-1.3,4.11)
  rrect7% 1.475x2.1 smd: 6(-2.462,3.75) 11(2.462,3.75)
  rrect100% 1.4x2.1 hole 0.6 slot 1.3 at 90 deg: 7(-3.95,1.45) 10(3.95,1.45)
  rrect7% 1.375x1.9 smd: 8(-0.937,1.45) 9(0.937,1.45)
  silkscreen extent 1.2,5.1 1.4,5.4
Murata_CSTCR_G [mm] "Murata"
  rect 0.4x2.6 smd: 1(-1.5,0) 2(0,0) 3(1.5,0)
Net-Tie_0805_HV_NoOverlay [mil] "0805_HV pads tied by 10mil copper trace which can be cut.  An 0805 part can be placed on pads."
  rect 50x63 smd paste-25: 1(-40,0) 2(40,0)
  Top Layer lines w10: -16,0 16,0
  Top Layer keep-out lines w1: -22,30.91 -22,-30.91 ; -14.96,30.91 14.96,30.91 ; 22,30.91 22,-30.91 ; -14.96,-30.91 14.96,-30.91
"NY PMS 440 0025 PH" [mm] "4-40 nylon screw and mounting hole"
  round 8 hole 3.2: 1(0,0)
PBC03SAAN [mm] "Sullins 100mil, 1x3, 230 mil above insulator"
  rect 1.65x1.65 hole 1.016: 1(-2.54,0)
  round 1.65 hole 1.016: 2(0,0) 3(2.54,0)
  silkscreen extent -3.81,-1.27 3.81,1.27
Phoenix_1902547 [mm] "TH, 2-Leads, Body 19.04x16mm, Pitch 9.52mm"
  rect 1.8x1.8 hole 1.3: 1(-4.76,3.1)
  round 1.8 hole 1.3: 2(4.76,3.1)
  silkscreen extent -10,-8 10.09,8
Phoenix_1904150 [mm] "TH, 3-Leads, Body 28.56x16mm, Pitch 9.52mm"
  rect 1.8x1.8 hole 1.3: 1(-9.52,3.1)
  round 1.8 hole 1.3: 2(0,3.1) 3(9.52,3.1)
  silkscreen extent -14.8,-8 14.85,8
PT0048A-MFG [mm]
  rrect33% 1.4x0.3 smd paste-1000 mask+0: 1(-4.25,2.75) 2(-4.25,2.25) 3(-4.25,1.75) 4(-4.25,1.25) 5(-4.25,0.75) 6(-4.25,0.25) 7(-4.25,-0.25) 8(-4.25,-0.75) 9(-4.25,-1.25) 10(-4.25,-1.75) 11(-4.25,-2.25) 12(-4.25,-2.75) 25(4.25,-2.75) 26(4.25,-2.25) 27(4.25,-1.75) 28(4.25,-1.25) 29(4.25,-0.75) 30(4.25,-0.25) 31(4.25,0.25) 32(4.25,0.75) 33(4.25,1.25) 34(4.25,1.75) 35(4.25,2.25) 36(4.25,2.75)
  rrect33% 0.3x1.4 smd paste-1000 mask+0: 13(-2.75,-4.25) 14(-2.25,-4.25) 15(-1.75,-4.25) 16(-1.25,-4.25) 17(-0.75,-4.25) 18(-0.25,-4.25) 19(0.25,-4.25) 20(0.75,-4.25) 21(1.25,-4.25) 22(1.75,-4.25) 23(2.25,-4.25) 24(2.75,-4.25) 37(2.75,4.25) 38(2.25,4.25) 39(1.75,4.25) 40(1.25,4.25) 41(0.75,4.25) 42(0.25,4.25) 43(-0.25,4.25) 44(-0.75,4.25) 45(-1.25,4.25) 46(-1.75,4.25) 47(-2.25,4.25) 48(-2.75,4.25)
  silkscreen extent -5.65,-3.6 3.6,3.6
REE0036A-MFG [mm]
  rrect50% 0.6x0.2 smd paste+0 mask+0: 1(-1.9,1.8) 2(-1.9,1.4) 3(-1.9,1) 4(-1.9,0.6) 5(-1.9,0.2) 6(-1.9,-0.2) 7(-1.9,-0.6) 8(-1.9,-1) 9(-1.9,-1.4) 10(-1.9,-1.8) 19(1.9,-1.8) 20(1.9,-1.4) 21(1.9,-1) 22(1.9,-0.6) 23(1.9,-0.2) 24(1.9,0.2) 25(1.9,0.6) 26(1.9,1) 27(1.9,1.4) 28(1.9,1.8)
  rrect50% 0.2x0.6 smd paste+0 mask+0: 11(-1.4,-2.4) 12(-1,-2.4) 13(-0.6,-2.4) 14(-0.2,-2.4) 15(0.2,-2.4) 16(0.6,-2.4) 17(1,-2.4) 18(1.4,-2.4) 29(1.4,2.4) 30(1,2.4) 31(0.6,2.4) 32(0.2,2.4) 33(-0.2,2.4) 34(-0.6,2.4) 35(-1,2.4) 36(-1.4,2.4)
  rrect7% 2.7x3.7 smd paste-1000 mask+0: 37(0,0)
  silkscreen extent -2.88,-2.55 2.05,2.55
SNT-100-BK-G [mil] "Samtec STEP model"
  round 1 on Mech3: 0(0,0)
SOD-323 [mm] "NXP recommended land pattern"
  rect 0.6x0.6 smd paste-0.05: 1(-1.1,0) 2(1.1,0)
  silkscreen extent -2.06,-0.86 1.53,0.86
SSOP28_N [mm] "SOP, 28-Leads, Body 10.2x5.3mm, Pitch 0.65mm, IPC Medium Density"
  oval 2.1x0.45 smd: 1(-3.45,4.225) 2(-3.45,3.575) 3(-3.45,2.925) 4(-3.45,2.275) 5(-3.45,1.625) 6(-3.45,0.975) 7(-3.45,0.325) 8(-3.45,-0.325) 9(-3.45,-0.975) 10(-3.45,-1.625) 11(-3.45,-2.275) 12(-3.45,-2.925) 13(-3.45,-3.575) 14(-3.45,-4.225) 15(3.45,-4.225) 16(3.45,-3.575) 17(3.45,-2.925) 18(3.45,-2.275) 19(3.45,-1.625) 20(3.45,-0.975) 21(3.45,-0.325) 22(3.45,0.325) 23(3.45,0.975) 24(3.45,1.625) 25(3.45,2.275) 26(3.45,2.925) 27(3.45,3.575) 28(3.45,4.225)
  silkscreen extent -3.57,-5.3 2,5.3
SW_434121025816 [mm] "SMD, 2-Leads, Body 6x3.9mm, Pitch 6.5mm"
  rect 1.5x1.4 smd: 1(-3.25,0) 2(3.25,0)
  silkscreen extent -3,-1.95 3,1.95
SW_B12AP [mm] "NKK Switches"
  rect 1.35x1.35 hole 0.85 paste+0: 1(-1,2.54)
  round 1.35 hole 0.85 paste+0: 2(-1,0) 3(-1,-2.54)
  silkscreen extent -4.27,-4.4 3.4,4.4
SW_G2xAP [mm] "TH, 6-Leads, Body 4.5x7mm, Pitch 2.54mm"
  rect 1.1x1.1 hole 0.6: 1(-2.54,1.27)
  round 1.1 hole 0.6: 2(0,1.27) 3(2.54,1.27) 4(-2.54,-1.27) 5(0,-1.27) 6(2.54,-1.27)
  silkscreen extent -3.51,-2.25 3.5,2.6
Testpoint_Keystone_Compact [mil] "Compact SMT test point"
  rect 185x135 smd: 1(0,0)
  silkscreen extent -110,-80 110,80
Testpoint_Keystone_Miniature [mil] "Miniature SMT test point"
  rect 135x70 smd: 1(0,0)
  silkscreen extent -78,-46 78,45
TI_Stacked_Overlay_Small [mil]
TSW-102-07-G-S [mm] "Samtec 100mil, 1x2, 230 mil above insulator"
  rrect50% 1.65x1.65 hole 1.016: 1(-1.27,0)
  round 1.65 hole 1.016: 2(1.27,0)
  silkscreen extent -3.17,-1.27 2.54,1.27
TSW-103-07-G-D [mm] "Samtec 100mil, 2x3, 230 mil above insulator"
  rect 1.65x1.65 hole 1.016: 1(-2.54,-1.27)
  round 1.65 hole 1.016: 2(-2.54,1.27) 3(0,-1.27) 4(0,1.27) 5(2.54,-1.27) 6(2.54,1.27)
  silkscreen extent -4.83,-2.54 3.81,2.54
TSW-104-07-G-S [mm] "Samtec 100mil, 1x4, 230 mil above insulator"
  rrect50% 1.65x1.65 hole 1.016: 1(-3.81,0)
  round 1.65 hole 1.016: 2(-1.27,0) 3(1.27,0) 4(3.81,0)
TSW-114-07-G-S [mm] "Samtec 100mil, 1x14, 230 mil above insulator"
  rrect6% 1.65x1.65 hole 1.016: 1(-16.51,0)
  round 1.65 hole 1.016: 2(-13.945,0.127) 3(-11.405,0.127) 4(-8.89,0) 5(-6.35,0) 6(-3.81,0) 7(-1.27,0) 8(1.27,0) 9(3.81,0) 10(6.35,0) 11(8.89,0) 12(11.43,0) 13(13.97,0) 14(16.51,0)
  silkscreen extent -17.78,-1.27 17.78,1.65
TSW-116-07-G-D [mm] "Samtec 100mil, 2x16, 230 mil above insulator"
  rrect6% 1.65x1.65 hole 1.016: 1(-19.05,-1.27)
  round 1.65 hole 1.016: 2(-19.05,1.27) 3(-16.51,-1.27) 4(-16.51,1.27) 5(-13.97,-1.27) 6(-13.97,1.27) 7(-11.43,-1.27) 8(-11.43,1.27) 9(-8.89,-1.27) 10(-8.89,1.27) 11(-6.35,-1.27) 12(-6.35,1.27) 13(-3.81,-1.27) 14(-3.81,1.27) 15(-1.27,-1.27) 16(-1.27,1.27) 17(1.27,-1.27) 18(1.27,1.27) 19(3.81,-1.27) 20(3.81,1.27) 21(6.35,-1.27) 22(6.35,1.27) 23(8.89,-1.27) 24(8.89,1.27) 25(11.43,-1.27) 26(11.43,1.27) 27(13.97,-1.27) 28(13.97,1.27) 29(16.51,-1.27) 30(16.51,1.27) 31(19.05,-1.27) 32(19.05,1.27)
  silkscreen extent -21.35,-2.54 20.32,2.54
WEEE_Minimum [mil] "WEEElie bin"
  silkscreen extent 22,-71 54,74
